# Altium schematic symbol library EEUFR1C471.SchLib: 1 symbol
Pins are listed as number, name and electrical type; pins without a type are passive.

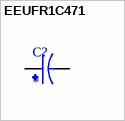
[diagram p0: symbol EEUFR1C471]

## EEUFR1C471
designator C?
Cap Aluminum Lytic 470uF 16V 20% (8 X 11.5mm) Radial 3.5mm 950mA 6000h 105C Bulk; MF: Panasonic; MP: EEUFR1C471
footprint CAPPRD350W60D800H1150
pins: N, P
